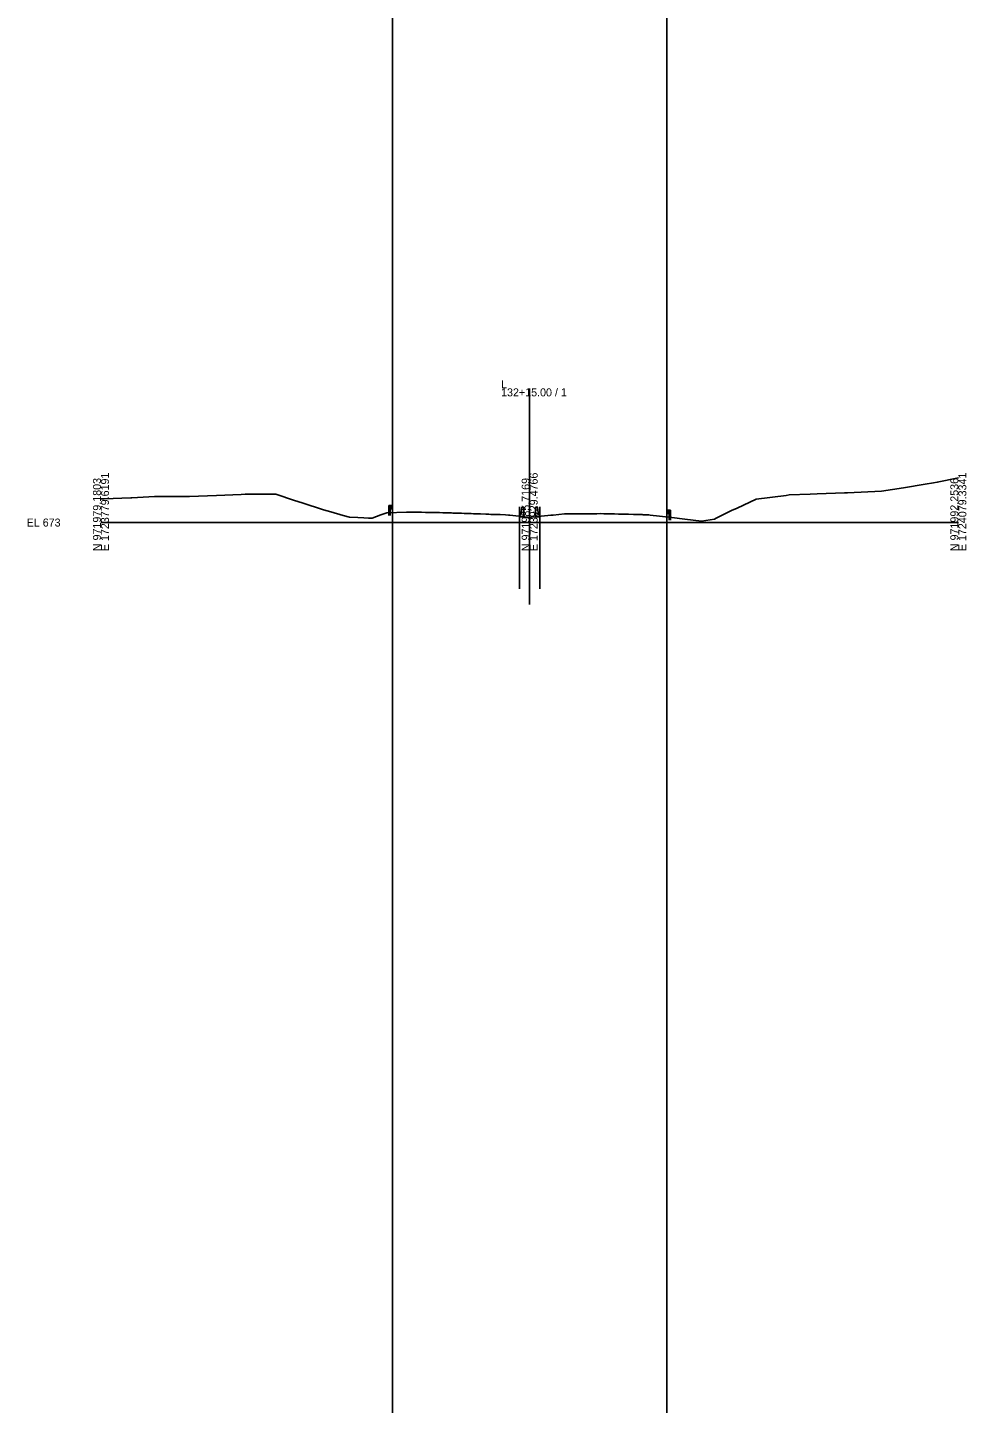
# Model space of a CAD drawing. Extents: x -26 to 303, y -29 to 15026.
# Drawn here: x -25.7 to 302.8, y 10691.7 to 11173.3 of the extents above; entities that cross this region are included whole.
import ezdxf

# ---------------------------------------------------------------- set-up
doc = ezdxf.new("R2010")
doc.units = 0
for name, color, linetype in [('Exist Cross Section Cell', 7, 'Continuous'), ('Exist XS Center Line Elevation Label', 7, 'Continuous'), ('Exist XS Ground Line', 7, 'Continuous'), ('Scratch_Level_0', 7, 'Continuous'), ('Typical Guardrail CELL', 7, 'Continuous'), ('Typical Median Barrier CELL', 7, 'Continuous')]:
    doc.layers.add(name, color=color, linetype=linetype)

msp = doc.modelspace()

# ---------------------------------------------------------------- linework, layer by layer
at = {"layer": 'Exist Cross Section Cell'}
for p, q in [((150, 11000), (150, 11046.97)), ((0, 11000), (150, 11000)), ((150, 11000), (300, 11000))]:
    msp.add_line(p, q, dxfattribs=at)
at = {"layer": 'Exist XS Ground Line'}
msp.add_lwpolyline([(0, 11008.28), (0.39, 11008.3), (1.16, 11008.33), (10.4, 11008.68), (10.75, 11008.69), (18.74, 11009.07), (20.49, 11009.15), (30.42, 11009.1), (30.95, 11009.12), (40.43, 11009.5), (49.11, 11009.86), (50.44, 11009.95), (52.45, 11009.89), (61.22, 11009.99), (67.69, 11007.78), (70.46, 11006.94), (77.89, 11004.47), (80.47, 11003.73), (84.8, 11002.48), (87.01, 11001.84), (89.87, 11001.79), (91.99, 11001.64), (93.65, 11001.59), (94.92, 11001.51), (97.93, 11002.7), (99.99, 11003.45), (106.93, 11003.65), (107.64, 11003.67), (107.97, 11003.66), (109.61, 11003.65), (111.37, 11003.65), (112.11, 11003.63), (113.61, 11003.58), (114.6, 11003.55), (116.01, 11003.54), (117.11, 11003.52), (118.41, 11003.48), (119.6, 11003.45), (120.8, 11003.41), (122.09, 11003.37), (122.69, 11003.35), (123.1, 11003.34), (123.78, 11003.32), (124.57, 11003.29), (126.11, 11003.24), (127.08, 11003.21), (128.73, 11003.17), (129.58, 11003.14), (130.34, 11003.11), (132.08, 11003.05), (132.75, 11003.03), (134.61, 11002.95), (135.22, 11002.93), (135.68, 11002.91), (136.4, 11002.88), (137.08, 11002.86), (137.52, 11002.84), (139.64, 11002.77), (141.6, 11002.71), (142.62, 11002.59), (143.09, 11002.54), (149.39, 11001.9), (150.19, 11001.81), (150.69, 11001.87), (156.39, 11002.43), (157.44, 11002.55), (158.26, 11002.63), (162.18, 11003.02), (162.56, 11003.06), (164.21, 11003.09), (165.52, 11003.09), (167.15, 11003.09), (168.77, 11003.1), (169.65, 11003.11), (170.62, 11003.11), (172.15, 11003.11), (173.56, 11003.11), (174.66, 11003.12), (176, 11003.1), (177.07, 11003.09), (178.06, 11003.06), (179.64, 11003.01), (181.05, 11002.99), (182.13, 11002.96), (183.12, 11002.94), (184.63, 11002.89), (186.29, 11002.85), (187.14, 11002.83), (188.64, 11002.79), (189.33, 11002.77), (189.66, 11002.75), (191.25, 11002.69), (191.75, 11002.67), (192.19, 11002.63), (199.77, 11001.8), (204.28, 11001.14), (210.14, 11000.52), (214.62, 11001.24), (215.24, 11001.54), (220.59, 11004.18), (222.62, 11005.08), (229.23, 11008.17), (239.76, 11009.53), (240.78, 11009.66), (248.2, 11009.99), (250.62, 11010.1), (260.11, 11010.37), (260.63, 11010.38), (261.2, 11010.37), (273.09, 11010.98), (280.75, 11012.11), (288.4, 11013.47), (291.32, 11013.9), (292.59, 11014.1), (300, 11015.66)], dxfattribs=at)
at = {"layer": 'Scratch_Level_0'}
for p, q in [((102, 15009.56), (102, -28.7)), ((198, 15009.56), (198, -28.7)), ((146.46, 11005.5), (146.46, 10976.8)), ((153.54, 11005.5), (153.54, 10976.8)), ((150, 11000), (150, 10971.3)), ((150, 11000), (150, 10971.3))]:
    msp.add_line(p, q, dxfattribs=at)
at = {"layer": 'Typical Guardrail CELL'}
for p, q in [((101.18, 11005.96), (100.68, 11005.96)), ((100.68, 11005.96), (100.68, 11003.47)), ((101.18, 11005.96), (101.18, 11003.47)), ((101.18, 11005.96), (101.68, 11005.96)), ((101.18, 11004.8), (101.68, 11004.8)), ((101.68, 11005.96), (101.68, 11004.8)), ((101.68, 11005.96), (101.97, 11005.75)), ((101.68, 11005.42), (101.97, 11005.63)), ((101.68, 11005.38), (101.68, 11005.42)), ((101.68, 11005.38), (101.68, 11005.33)), ((101.68, 11005.33), (101.97, 11005.13)), ((101.68, 11004.8), (101.97, 11005)), ((198.32, 11004.34), (198.03, 11004.14)), ((198.32, 11003.81), (198.03, 11004.01)), ((198.32, 11003.71), (198.03, 11003.51)), ((198.82, 11004.34), (198.32, 11004.34)), ((198.32, 11004.34), (198.32, 11003.18)), ((198.32, 11003.76), (198.32, 11003.81)), ((198.32, 11003.76), (198.32, 11003.71)), ((198.82, 11004.34), (198.82, 11001.85)), ((198.82, 11004.34), (199.32, 11004.34)), ((199.32, 11004.34), (199.32, 11001.85)), ((101.18, 11003.47), (100.68, 11003.47)), ((100.68, 11003.47), (100.68, 11002.46)), ((101.18, 11003.47), (101.18, 11002.46)), ((198.32, 11003.18), (198.03, 11003.38)), ((198.82, 11003.18), (198.32, 11003.18)), ((198.82, 11001.85), (199.32, 11001.85)), ((198.82, 11001.85), (198.82, 11000.85)), ((199.32, 11001.85), (199.32, 11000.85))]:
    msp.add_line(p, q, dxfattribs=at)
for centre, start, end in [((101.92, 11005.69), 304.9888, 54.997), ((101.92, 11005.06), 304.9634, 54.9941), ((198.08, 11004.07), 125.003, 235.0112), ((198.08, 11003.45), 125.0059, 235.0366)]:
    msp.add_arc(centre, 0.0776, start, end, dxfattribs=at)
at = {"layer": 'Typical Median Barrier CELL'}
for p, q in [((147.07, 11003.44), (147.29, 11005.4)), ((147.29, 11005.4), (147.96, 11005.4)), ((147.96, 11005.4), (147.96, 11001.98)), ((152.71, 11005.4), (152.04, 11005.4)), ((152.04, 11005.4), (152.04, 11001.98)), ((152.93, 11003.44), (152.71, 11005.4)), ((146.46, 11002.4), (146.92, 11003.05)), ((146.46, 11001.98), (146.46, 11002.4)), ((147.96, 11001.98), (146.46, 11001.98)), ((152.04, 11001.98), (153.54, 11001.98)), ((153.54, 11002.4), (153.08, 11003.05)), ((153.54, 11001.98), (153.54, 11002.4))]:
    msp.add_line(p, q, dxfattribs=at)
for centre, start, end in [((146.24, 11003.53), 325.0039, 353.9447), ((153.76, 11003.53), 186.0553, 214.9961)]:
    msp.add_arc(centre, 0.833, start, end, dxfattribs=at)

# ---------------------------------------------------------------- texts
at = {"layer": 'Exist Cross Section Cell'}
for s, p in [('132+15.00 / 1', (140, 11044.17)), ('L', (140, 11046.97)), ('EL 673', (-26, 10998.6))]:
    msp.add_text(s, height=2.8, dxfattribs=at).set_placement(p)
for s, p in [('N 971979.1803', (0, 10990)), ('E 1723779.6191', (2.8, 10990)), ('N 971985.7169', (150, 10990)), ('E 1723929.4766', (152.8, 10990)), ('N 971992.2536', (300, 10990)), ('E 1724079.3341', (302.8, 10990))]:
    msp.add_text(s, height=2.8, rotation=90, dxfattribs=at).set_placement(p)
at = {"layer": 'Exist XS Center Line Elevation Label'}
msp.add_text('674.83', height=0.18, dxfattribs=at).set_placement((149.62, 11001.34))

doc.saveas('drawing.dxf')
